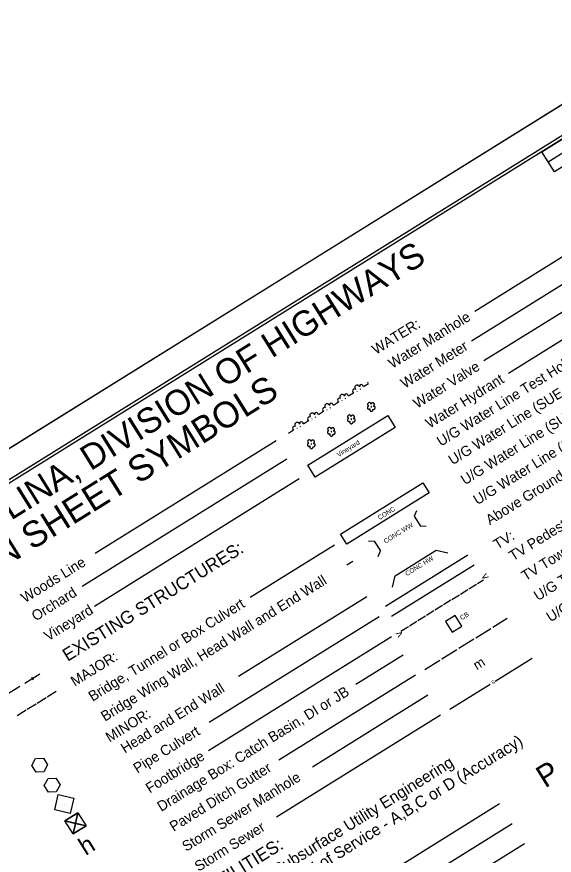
# Model space of a CAD drawing. Extents: x 2046091 to 2048102, y 759061 to 760885.
# Drawn here: x 2046937 to 2047393, y 760172 to 760885 of the extents above; entities that cross this region are included whole.
import ezdxf

# ---------------------------------------------------------------- set-up
doc = ezdxf.new("R2010")
doc.units = 0
for name, color, linetype in [('Matchline Text', 7, 'Continuous'), ('Sheet Cutting Line CELL', 7, 'Continuous'), ('Sheet Plot Border Inside CELL', 7, 'Continuous'), ('Sheet Plot Border Outside CELL', 7, 'Continuous'), ('Sheet Symbology CELL', 7, 'Continuous')]:
    doc.layers.add(name, color=color, linetype=linetype)

msp = doc.modelspace()

# ---------------------------------------------------------------- linework, layer by layer
at = {"layer": 'Matchline Text'}
for p, q in [((2046956.23, 760248.65), (2046956.23, 760248.65)), ((2046966.78, 760231.7), (2046966.78, 760231.7)), ((2046976.98, 760215.58), (2046976.98, 760215.58)), ((2046986.6, 760199.19), (2046986.6, 760199.19))]:
    msp.add_line(p, q, dxfattribs=at)
for points in [[(2046959.75, 760243.01), (2046953.09, 760242.74), (2046949.57, 760248.38), (2046952.71, 760254.3), (2046959.37, 760254.57), (2046962.93, 760248.87), (2046959.75, 760243.01)], [(2046988.67, 760208.11), (2046984.52, 760190.24), (2046986.6, 760199.17), (2046995.53, 760197.1), (2046977.66, 760201.25)], [(2046986.6, 760199.17), (2046988.67, 760208.11), (2046977.66, 760201.25), (2046986.6, 760199.17)], [(2046986.6, 760199.17), (2046984.52, 760190.24), (2046995.53, 760197.1), (2046986.6, 760199.17)]]:
    msp.add_lwpolyline(points, dxfattribs=at)
for points in [[(2046960.05, 760231.48), (2046963.29, 760237.36), (2046969.98, 760237.72), (2046973.45, 760231.97), (2046970.28, 760225.98), (2046963.65, 760225.7)], [(2046968.98, 760210.63), (2046972, 760223.66), (2046985.05, 760220.63), (2046982.03, 760207.6)], [(2046977.66, 760201.25), (2046988.67, 760208.11), (2046995.53, 760197.1), (2046984.52, 760190.24)]]:
    msp.add_lwpolyline(points, close=True, dxfattribs=at)
at = {"layer": 'Sheet Cutting Line CELL'}
msp.add_line((2047520.01, 760885.29), (2046090.62, 759994.95), dxfattribs=at)
at = {"layer": 'Sheet Plot Border Inside CELL'}
msp.add_lwpolyline([(2046671.37, 759087.19), (2048085.9, 759968.28), (2047528.06, 760863.85), (2046113.53, 759982.76)], close=True, dxfattribs=at)
at = {"layer": 'Sheet Plot Border Outside CELL'}
msp.add_lwpolyline([(2046672.2, 759061.26), (2048101.59, 759951.6), (2047520.01, 760885.29), (2046090.62, 759994.95)], close=True, dxfattribs=at)
at = {"layer": 'Sheet Symbology CELL'}
for p, q in [((2047388.27, 760761.95), (2047524.11, 760846.56)), ((2047463.64, 760720.56), (2047325.8, 760634.71)), ((2047474.21, 760703.59), (2047323.09, 760609.46)), ((2047484.79, 760686.61), (2047333.67, 760592.48)), ((2047495.36, 760669.64), (2047354.64, 760581.98)), ((2047231.27, 760570.81), (2047235.52, 760573.46)), ((2047225.55, 760566.66), (2047225.98, 760566.93)), ((2047228.52, 760568.51), (2047228.95, 760568.78)), ((2047212.82, 760558.73), (2047213.25, 760559)), ((2047215.79, 760560.58), (2047216.22, 760560.85)), ((2047218.54, 760562.88), (2047222.78, 760565.53)), ((2047203.06, 760552.65), (2047203.48, 760552.92)), ((2047205.81, 760554.95), (2047210.05, 760557.6)), ((2047190.33, 760544.72), (2047190.75, 760544.99)), ((2047193.08, 760547.02), (2047197.32, 760549.67)), ((2047200.09, 760550.8), (2047200.51, 760551.07)), ((2047180.34, 760539.09), (2047184.59, 760541.74)), ((2047187.36, 760542.87), (2047187.78, 760543.14)), ((2047167.61, 760531.16), (2047171.86, 760533.81)), ((2047174.62, 760534.94), (2047175.05, 760535.21)), ((2047177.6, 760536.79), (2047178.02, 760537.06)), ((2047157.09, 760524.61), (2047003.35, 760428.85)), ((2047166.09, 760509.09), (2046992.14, 760400.74)), ((2047176.67, 760492.12), (2047002.71, 760383.77)), ((2047276.36, 760465.1), (2047274.39, 760460.5)), ((2047274.39, 760460.5), (2047279.68, 760452.01)), ((2047284.67, 760451.75), (2047279.68, 760452.01)), ((2047235.45, 760439.61), (2047240.44, 760439.35)), ((2047240.44, 760439.35), (2047245.73, 760430.86)), ((2047206.58, 760435.93), (2047134.92, 760391.3)), ((2047243.76, 760426.27), (2047245.73, 760430.86)), ((2047258.15, 760409.74), (2047293.16, 760431.55)), ((2047293.16, 760431.55), (2047302.91, 760429.29)), ((2047249.89, 760383.98), (2047319.92, 760427.6)), ((2047217.15, 760418.96), (2047222.23, 760422.12)), ((2047255.18, 760375.5), (2047325.21, 760419.11)), ((2047255.88, 760400), (2047258.15, 760409.74)), ((2047320.83, 760398.72), (2047327.2, 760402.68)), ((2047328.04, 760403.21), (2047333.14, 760406.38)), ((2047313.61, 760394.22), (2047319.98, 760398.19)), ((2047234.07, 760391.8), (2047125.17, 760323.97)), ((2047299.18, 760385.23), (2047305.55, 760389.2)), ((2047306.4, 760389.73), (2047312.77, 760393.69)), ((2047291.97, 760380.74), (2047298.34, 760384.71)), ((2047244.64, 760374.82), (2047100.19, 760284.84)), ((2047277.54, 760371.75), (2047283.91, 760375.72)), ((2047284.76, 760376.25), (2047291.12, 760380.21)), ((2047341.15, 760366.09), (2047353.46, 760373.76)), ((2047263.11, 760362.76), (2047269.48, 760366.73)), ((2047270.33, 760367.26), (2047276.69, 760371.22)), ((2047326.72, 760357.1), (2047339.45, 760365.03)), ((2047255.22, 760357.85), (2047099.48, 760260.84)), ((2047312.29, 760348.12), (2047325.02, 760356.05)), ((2047297.86, 760339.13), (2047310.59, 760347.06)), ((2047264.96, 760342.2), (2047224.9, 760317.24)), ((2047283.43, 760330.14), (2047296.16, 760338.07)), ((2047343.22, 760320.26), (2047374.61, 760339.81)), ((2046943.54, 760318.5), (2046956.27, 760326.43)), ((2046949.24, 760323.52), (2046950.57, 760321.4)), ((2047275.54, 760325.22), (2047159.29, 760252.82)), ((2047304.58, 760296.19), (2047338.98, 760317.61)), ((2046926.56, 760307.92), (2046939.29, 760315.85)), ((2046962.6, 760306.81), (2046970.24, 760311.56)), ((2046954.11, 760301.52), (2046961.75, 760306.28)), ((2047286.11, 760308.25), (2047187.93, 760247.09)), ((2046937.14, 760290.95), (2046944.78, 760295.7)), ((2046945.62, 760296.23), (2046953.26, 760300.99)), ((2047296.69, 760291.27), (2047157.31, 760204.46)), ((2047347, 760215.77), (2047229.27, 760142.44)), ((2047357.57, 760198.8), (2047246.45, 760129.58)), ((2047368.14, 760181.82), (2047264.16, 760117.05))]:
    msp.add_line(p, q, dxfattribs=at)
for points in [[(2047518.8, 760855.08), (2046245.59, 760062.02), (2046800.2, 759171.64), (2048073.4, 759964.7)], [(2047382.96, 760770.47), (2047518.8, 760855.08), (2047529.39, 760838.07), (2047393.55, 760753.46)], [(2047306.6, 760361.87), (2047314.75, 760366.95), (2047309.13, 760375.98), (2047300.97, 760370.9)]]:
    msp.add_lwpolyline(points, close=True, dxfattribs=at)
for points in [[(2047237.69, 760555.75), (2047237.66, 760556.09), (2047237.54, 760556.37), (2047237.34, 760556.6), (2047237.14, 760556.83), (2047236.88, 760556.96), (2047236.62, 760557.09), (2047236.3, 760557.13), (2047236.01, 760557.12), (2047235.66, 760557.02), (2047235.45, 760556.89), (2047235.22, 760556.69), (2047235.02, 760556.45), (2047234.89, 760556.19), (2047234.78, 760555.89), (2047234.81, 760555.55), (2047234.86, 760555.29), (2047234.98, 760555.01), (2047235.13, 760554.75), (2047235.34, 760554.52), (2047235.59, 760554.39), (2047235.92, 760554.24), (2047235.63, 760554.24), (2047235.35, 760554.12), (2047235.1, 760553.96), (2047234.94, 760553.74), (2047234.78, 760553.53), (2047234.67, 760553.23), (2047234.61, 760552.95), (2047234.61, 760552.66), (2047234.7, 760552.42), (2047234.84, 760552.1), (2047235.02, 760551.91), (2047235.24, 760551.75), (2047235.54, 760551.64), (2047235.77, 760551.55), (2047236.06, 760551.56), (2047236.4, 760551.59), (2047236.63, 760551.68), (2047236.89, 760551.84), (2047236.73, 760551.62), (2047236.62, 760551.32), (2047236.6, 760551.07), (2047236.68, 760550.76), (2047236.75, 760550.46), (2047236.88, 760550.24), (2047237.08, 760550.02), (2047237.34, 760549.88), (2047237.6, 760549.75), (2047237.88, 760549.69), (2047238.17, 760549.69), (2047238.43, 760549.74), (2047238.69, 760549.9), (2047238.94, 760550.05), (2047239.13, 760550.23), (2047239.24, 760550.53), (2047239.37, 760550.79), (2047239.34, 760551.3)], [(2047237.89, 760553.82), (2047237.77, 760553.74), (2047237.71, 760553.64), (2047237.65, 760553.55), (2047237.73, 760553.42), (2047237.78, 760553.34), (2047237.92, 760553.31), (2047238.05, 760553.38), (2047238.13, 760553.44), (2047238.16, 760553.58), (2047238.13, 760553.73), (2047238.03, 760553.79), (2047237.89, 760553.82)], [(2047239.34, 760551.3), (2047240.04, 760551.33), (2047240.34, 760551.4), (2047240.63, 760551.51), (2047240.85, 760551.72), (2047241.01, 760551.93), (2047241.15, 760552.19), (2047241.25, 760552.49), (2047241.25, 760552.79), (2047241.2, 760553.05), (2047241.13, 760553.36), (2047240.93, 760553.59), (2047240.72, 760553.81), (2047240.4, 760553.96), (2047240.16, 760554.05), (2047239.87, 760554.05), (2047239.54, 760554.02), (2047239.82, 760554.13), (2047240.12, 760554.32), (2047240.28, 760554.54), (2047240.45, 760554.82), (2047240.58, 760555.08), (2047240.62, 760555.4), (2047240.59, 760555.73), (2047240.47, 760556.01), (2047240.36, 760556.3), (2047240.16, 760556.52), (2047239.91, 760556.73), (2047239.61, 760556.83), (2047239.27, 760556.91), (2047238.97, 760556.91), (2047238.67, 760556.83), (2047238.39, 760556.72), (2047238.13, 760556.56), (2047237.93, 760556.32), (2047237.8, 760556.06), (2047237.69, 760555.75)], [(2047184.01, 760503.76), (2047251.92, 760546.06), (2047258.26, 760535.87), (2047190.36, 760493.58), (2047184.01, 760503.76)], [(2047220.71, 760545.18), (2047220.68, 760545.51), (2047220.57, 760545.8), (2047220.37, 760546.02), (2047220.16, 760546.25), (2047219.91, 760546.38), (2047219.65, 760546.52), (2047219.33, 760546.55), (2047219.04, 760546.55), (2047218.69, 760546.45), (2047218.47, 760546.32), (2047218.25, 760546.12), (2047218.04, 760545.87), (2047217.91, 760545.61), (2047217.8, 760545.31), (2047217.84, 760544.98), (2047217.88, 760544.71), (2047218, 760544.43), (2047218.16, 760544.18), (2047218.36, 760543.95), (2047218.62, 760543.82), (2047218.95, 760543.67), (2047218.66, 760543.66), (2047218.37, 760543.55), (2047218.12, 760543.39), (2047217.96, 760543.17), (2047217.8, 760542.95), (2047217.69, 760542.65), (2047217.63, 760542.38), (2047217.64, 760542.08), (2047217.73, 760541.85), (2047217.87, 760541.52), (2047218.04, 760541.34), (2047218.26, 760541.18), (2047218.56, 760541.07), (2047218.79, 760540.98), (2047219.09, 760540.98), (2047219.42, 760541.02), (2047219.66, 760541.11), (2047219.91, 760541.26), (2047219.75, 760541.05), (2047219.65, 760540.75), (2047219.63, 760540.5), (2047219.7, 760540.19), (2047219.77, 760539.88), (2047219.91, 760539.67), (2047220.11, 760539.44), (2047220.37, 760539.31), (2047220.63, 760539.18), (2047220.9, 760539.11), (2047221.19, 760539.12), (2047221.46, 760539.16), (2047221.71, 760539.32), (2047221.97, 760539.48), (2047222.15, 760539.66), (2047222.26, 760539.96), (2047222.39, 760540.22), (2047222.37, 760540.73)], [(2047222.37, 760540.73), (2047223.06, 760540.75), (2047223.37, 760540.82), (2047223.65, 760540.94), (2047223.88, 760541.14), (2047224.04, 760541.36), (2047224.17, 760541.62), (2047224.28, 760541.92), (2047224.27, 760542.21), (2047224.22, 760542.48), (2047224.15, 760542.78), (2047223.95, 760543.01), (2047223.75, 760543.24), (2047223.42, 760543.39), (2047223.19, 760543.48), (2047222.9, 760543.48), (2047222.56, 760543.44), (2047222.84, 760543.56), (2047223.14, 760543.75), (2047223.3, 760543.96), (2047223.47, 760544.25), (2047223.61, 760544.51), (2047223.64, 760544.83), (2047223.61, 760545.16), (2047223.5, 760545.44), (2047223.38, 760545.72), (2047223.18, 760545.95), (2047222.94, 760546.15), (2047222.63, 760546.26), (2047222.29, 760546.34), (2047222, 760546.33), (2047221.69, 760546.26), (2047221.41, 760546.14), (2047221.16, 760545.98), (2047220.95, 760545.74), (2047220.82, 760545.48), (2047220.71, 760545.18)], [(2047220.92, 760543.25), (2047220.79, 760543.17), (2047220.73, 760543.07), (2047220.67, 760542.98), (2047220.75, 760542.85), (2047220.81, 760542.76), (2047220.94, 760542.73), (2047221.07, 760542.81), (2047221.16, 760542.86), (2047221.19, 760543), (2047221.15, 760543.15), (2047221.06, 760543.21), (2047220.92, 760543.25)], [(2047203.74, 760534.61), (2047203.71, 760534.94), (2047203.59, 760535.22), (2047203.39, 760535.45), (2047203.19, 760535.68), (2047202.93, 760535.81), (2047202.67, 760535.94), (2047202.35, 760535.98), (2047202.06, 760535.98), (2047201.71, 760535.88), (2047201.5, 760535.74), (2047201.27, 760535.54), (2047201.07, 760535.3), (2047200.94, 760535.04), (2047200.83, 760534.74), (2047200.86, 760534.4), (2047200.91, 760534.14), (2047201.02, 760533.86), (2047201.18, 760533.6), (2047201.38, 760533.37), (2047201.64, 760533.24), (2047201.97, 760533.09), (2047201.68, 760533.09), (2047201.4, 760532.97), (2047201.14, 760532.81), (2047200.98, 760532.6), (2047200.83, 760532.38), (2047200.72, 760532.08), (2047200.65, 760531.8), (2047200.66, 760531.51), (2047200.75, 760531.27), (2047200.89, 760530.95), (2047201.07, 760530.76), (2047201.28, 760530.6), (2047201.59, 760530.5), (2047201.82, 760530.41), (2047202.11, 760530.41), (2047202.44, 760530.44), (2047202.68, 760530.53), (2047202.94, 760530.69), (2047202.78, 760530.47), (2047202.67, 760530.17), (2047202.65, 760529.92), (2047202.72, 760529.61), (2047202.8, 760529.31), (2047202.93, 760529.1), (2047203.13, 760528.87), (2047203.39, 760528.73), (2047203.65, 760528.6), (2047203.93, 760528.54), (2047204.22, 760528.54), (2047204.48, 760528.59), (2047204.74, 760528.75), (2047204.99, 760528.91), (2047205.18, 760529.08), (2047205.28, 760529.38), (2047205.42, 760529.64), (2047205.39, 760530.16)], [(2047203.94, 760532.67), (2047203.81, 760532.59), (2047203.76, 760532.5), (2047203.7, 760532.4), (2047203.78, 760532.27), (2047203.83, 760532.19), (2047203.97, 760532.16), (2047204.1, 760532.24), (2047204.18, 760532.29), (2047204.21, 760532.43), (2047204.18, 760532.58), (2047204.08, 760532.64), (2047203.94, 760532.67)], [(2047205.39, 760530.16), (2047206.08, 760530.18), (2047206.39, 760530.25), (2047206.67, 760530.37), (2047206.9, 760530.57), (2047207.06, 760530.78), (2047207.19, 760531.04), (2047207.3, 760531.35), (2047207.3, 760531.64), (2047207.25, 760531.9), (2047207.17, 760532.21), (2047206.97, 760532.44), (2047206.77, 760532.67), (2047206.44, 760532.82), (2047206.21, 760532.91), (2047205.92, 760532.9), (2047205.59, 760532.87), (2047205.87, 760532.99), (2047206.16, 760533.17), (2047206.32, 760533.39), (2047206.5, 760533.67), (2047206.63, 760533.93), (2047206.67, 760534.25), (2047206.64, 760534.59), (2047206.52, 760534.87), (2047206.4, 760535.15), (2047206.2, 760535.38), (2047205.96, 760535.58), (2047205.66, 760535.68), (2047205.31, 760535.76), (2047205.02, 760535.76), (2047204.72, 760535.69), (2047204.43, 760535.57), (2047204.18, 760535.41), (2047203.98, 760535.17), (2047203.84, 760534.91), (2047203.74, 760534.61)], [(2047186.76, 760524.03), (2047186.73, 760524.37), (2047186.61, 760524.65), (2047186.41, 760524.88), (2047186.21, 760525.1), (2047185.95, 760525.24), (2047185.69, 760525.37), (2047185.38, 760525.41), (2047185.08, 760525.4), (2047184.73, 760525.3), (2047184.52, 760525.17), (2047184.29, 760524.97), (2047184.09, 760524.72), (2047183.96, 760524.47), (2047183.85, 760524.16), (2047183.88, 760523.83), (2047183.93, 760523.56), (2047184.05, 760523.28), (2047184.21, 760523.03), (2047184.41, 760522.8), (2047184.67, 760522.67), (2047184.99, 760522.52), (2047184.7, 760522.51), (2047184.42, 760522.4), (2047184.17, 760522.24), (2047184.01, 760522.02), (2047183.85, 760521.8), (2047183.74, 760521.5), (2047183.68, 760521.23), (2047183.68, 760520.94), (2047183.77, 760520.7), (2047183.92, 760520.37), (2047184.09, 760520.19), (2047184.31, 760520.03), (2047184.61, 760519.92), (2047184.84, 760519.83), (2047185.13, 760519.84), (2047185.47, 760519.87), (2047185.71, 760519.96), (2047185.96, 760520.12), (2047185.8, 760519.9), (2047185.7, 760519.6), (2047185.67, 760519.35), (2047185.75, 760519.04), (2047185.82, 760518.73), (2047185.95, 760518.52), (2047186.15, 760518.29), (2047186.41, 760518.16), (2047186.67, 760518.03), (2047186.95, 760517.96), (2047187.24, 760517.97), (2047187.51, 760518.02), (2047187.76, 760518.17), (2047188.01, 760518.33), (2047188.2, 760518.51), (2047188.31, 760518.81), (2047188.44, 760519.07), (2047188.41, 760519.58)], [(2047188.41, 760519.58), (2047189.11, 760519.6), (2047189.42, 760519.68), (2047189.7, 760519.79), (2047189.93, 760519.99), (2047190.08, 760520.21), (2047190.22, 760520.47), (2047190.32, 760520.77), (2047190.32, 760521.06), (2047190.27, 760521.33), (2047190.2, 760521.64), (2047190, 760521.86), (2047189.8, 760522.09), (2047189.47, 760522.24), (2047189.23, 760522.33), (2047188.94, 760522.33), (2047188.61, 760522.3), (2047188.89, 760522.41), (2047189.19, 760522.6), (2047189.35, 760522.81), (2047189.52, 760523.1), (2047189.65, 760523.36), (2047189.69, 760523.68), (2047189.66, 760524.01), (2047189.55, 760524.29), (2047189.43, 760524.57), (2047189.23, 760524.8), (2047188.98, 760525), (2047188.68, 760525.11), (2047188.34, 760525.19), (2047188.05, 760525.19), (2047187.74, 760525.11), (2047187.46, 760525), (2047187.2, 760524.84), (2047187, 760524.59), (2047186.87, 760524.33), (2047186.76, 760524.03)], [(2047186.97, 760522.1), (2047186.84, 760522.02), (2047186.78, 760521.92), (2047186.72, 760521.83), (2047186.8, 760521.7), (2047186.85, 760521.61), (2047186.99, 760521.58), (2047187.12, 760521.66), (2047187.2, 760521.72), (2047187.24, 760521.85), (2047187.2, 760522.01), (2047187.1, 760522.06), (2047186.97, 760522.1)], [(2047211.83, 760445.09), (2047281.86, 760488.71), (2047287.14, 760480.22), (2047217.12, 760436.61), (2047211.83, 760445.09)]]:
    msp.add_lwpolyline(points, dxfattribs=at)
for centre, radius, start, end in [((2047236.21, 760575.09), 1.58, 188.16905, 235.66702), ((2047223.48, 760567.15), 1.58, 50.35298, 251.14955), ((2047225.92, 760569.85), 2.06, 17.88179, 225.95428), ((2047229.42, 760570.86), 1.58, 352.68651, 193.48308), ((2047210.74, 760559.22), 1.58, 50.35298, 251.14955), ((2047213.19, 760561.92), 2.06, 17.88179, 225.95428), ((2047216.69, 760562.93), 1.58, 352.68651, 193.48308), ((2047198.01, 760551.29), 1.58, 50.35298, 251.14955), ((2047200.45, 760553.99), 2.06, 17.88179, 225.95428), ((2047203.95, 760554.99), 1.58, 352.68651, 193.48308), ((2047185.28, 760543.36), 1.58, 50.35298, 251.14955), ((2047187.72, 760546.06), 2.06, 17.88179, 225.95428), ((2047191.22, 760547.06), 1.58, 352.68651, 193.48308), ((2047174.99, 760538.13), 2.06, 17.88179, 225.95428), ((2047178.49, 760539.13), 1.58, 352.68651, 193.48308), ((2047172.55, 760535.43), 1.58, 50.35298, 251.14955)]:
    msp.add_arc(centre, radius, start, end, dxfattribs=at)

# ---------------------------------------------------------------- texts
for s, height, rotation, p in [('STATE OF NORTH CAROLINA, DIVISION OF HIGHWAYS', 21.419, 31.91803, (2046642.81, 760276.5)), ('U/G Water Line Test Hole (SUE - LOS A)*', 8.75, 31.91803, (2047297.07, 760519.47)), ('Water Manhole', 8.75, 31.91803, (2047255.79, 760585.75)), ('WATER:', 8.75, 31.91803, (2047241.87, 760597.55)), ('Water Meter', 8.75, 31.91803, (2047266.36, 760568.78)), ('U/G Water Line (SUE - LOS B)*', 8.75, 31.91803, (2047306.93, 760503.64)), ('Water Valve', 8.75, 31.91803, (2047276.94, 760551.8)), ('Water Hydrant', 8.75, 31.91803, (2047287.51, 760534.82)), ('U/G Water Line (SUE - LOS C)*', 8.75, 31.91803, (2047317.5, 760486.67)), ('CONVENTIONAL  PLAN SHEET SYMBOLS', 22.0323, 31.91803, (2046666.04, 760254.59)), ('U/G Water Line (SUE - LOS D)*', 8.75, 31.91803, (2047328.08, 760469.69)), ('Vineyard', 4, 31.91805, (2047210.16, 760510.63)), ('Above Ground Water Line', 8.75, 31.91803, (2047338.65, 760452.72)), ('CONC', 4, 31.91803, (2047244.95, 760457.05)), ('U/G TV Test Hole (SUE - LOS A)*', 8.75, 31.91803, (2047390.14, 760370.06)), ('TV Pedestal', 8.75, 31.91803, (2047358.33, 760422.04)), ('U/G TV Cable Hand Hole', 8.75, 31.91803, (2047379.48, 760388.08)), ('CONC WW', 4, 31.91805, (2047249.98, 760437.05)), ('TV:', 8.75, 31.91803, (2047345.11, 760431.81)), ('EXISTING STRUCTURES:', 11, 31.91803, (2046979.91, 760336.51)), ('TV Tower', 8.75, 31.91803, (2047368.9, 760405.06)), ('Woods Line', 8.75, 31.91803, (2046943.75, 760386.39)), ('CONC HW', 4, 31.91803, (2047268.29, 760409.39)), ('Bridge Wing Wall, Head Wall and End Wall', 8.75, 31.91803, (2047011.63, 760285.58)), ('v', 6.6, 302.15889, (2047331.15, 760409.55)), ('Orchard', 8.75, 31.91803, (2046952.75, 760370.88)), ('Bridge, Tunnel or Box Culvert', 8.75, 31.91803, (2047001.06, 760302.56)), ('Vineyard', 8.75, 31.91803, (2046963.32, 760353.9)), ('CB', 4, 31.91803, (2047314.81, 760371.86)), ('v', 6.6, 121.67718, (2047265.08, 760359.59)), ('MAJOR:', 8.75, 31.91803, (2046985.96, 760315.4)), ('m', 8.25, 31.91803, (2047327.7, 760329.29)), ('Head and End Wall', 8.75, 31.91803, (2047028.55, 760258.42)), ('S', 3, 31.91803, (2047341.13, 760317.19)), ('Drainage Box: Catch Basin, DI or JB', 8.75, 31.91803, (2047059.45, 760208.84)), ('MINOR:', 8.75, 31.91803, (2047015.63, 760267.76)), ('Pipe Culvert', 8.75, 31.91803, (2047039.12, 760241.46)), ('LOS - Level of Service - A,B,C or D (Accuracy) ', 9.9, 31.91803, (2047134.8, 760121.51)), ('Footbridge', 8.75, 31.91803, (2047049.7, 760224.49)), ('* SUE - Subsurface Utility Engineering', 9.9, 31.91803, (2047117.86, 760129.3)), ('Paved Ditch Gutter', 8.75, 31.91803, (2047070.03, 760191.85)), ('P', 18.75, 31.91803, (2047385.6, 760228.77)), ('Storm Sewer Manhole', 8.75, 31.91803, (2047080.6, 760174.88)), ('Storm Sewer', 8.75, 31.91803, (2047091.18, 760157.9)), ('h', 15, 31.91803, (2046995.22, 760171.36)), ('UTILITIES:', 11, 31.91803, (2047102.46, 760139.76))]:
    msp.add_text(s, height=height, rotation=rotation, dxfattribs=at).set_placement(p)

doc.saveas('drawing.dxf')
